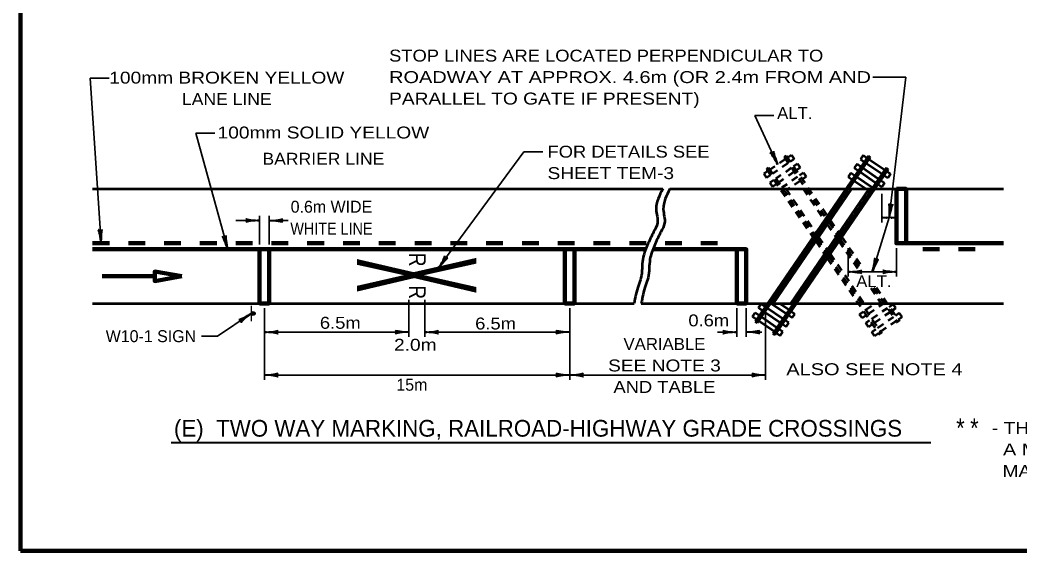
# Model space of a CAD drawing. Extents: x -90 to 765, y -1136 to -592.
# Drawn here: x -32.9 to 218.6, y -1124.2 to -990.6 of the extents above; entities that cross this region are included whole.
import ezdxf
from ezdxf.enums import TextEntityAlignment as Align

# ---------------------------------------------------------------- set-up
doc = ezdxf.new("R2010")
doc.units = 0
doc.header["$LTSCALE"] = 1.2
doc.linetypes.add('SHORT_DASHED', pattern=[2.7, 1.5, -1.2])
doc.layers.add('1', color=7, linetype='Continuous', lineweight=90)
doc.layers.add('4', color=7, linetype='Continuous', lineweight=25)

msp = doc.modelspace()

# ---------------------------------------------------------------- hatches: boundary and pattern name
at = {"layer": '4'}
msp.add_hatch(color=256, dxfattribs=at).paths.add_polyline_path([(25.74, -1064.932, 1), (25.74, -1063.948, 1)])

# ---------------------------------------------------------------- linework, layer by layer
at = {"layer": '1', "lineweight": 35}
for p, q in [((-15.299, -1005.233), (-10.499, -1005.233)), ((-12.544, -1046.773), (-15.299, -1005.233)), ((181.609, -1004.973), (189.928, -1004.973)), ((157.663, -1026.973), (151.918, -1014.613)), ((151.918, -1014.613), (156.718, -1014.613)), ((19.318, -1048.273), (11.319, -1019.091)), ((11.319, -1019.091), (16.119, -1019.091)), ((72.303, -1053.024), (93.792, -1023.775)), ((93.792, -1023.775), (98.592, -1023.775)), ((183.879, -1034.323), (183.879, -1041.523)), ((21.356, -1041.073), (27.356, -1041.073)), ((27.356, -1047.073), (27.356, -1039.873)), ((29.756, -1047.073), (29.756, -1039.873)), ((29.756, -1041.073), (34.556, -1041.073)), ((183.879, -1040.323), (187.556, -1040.323)), ((175.42, -1047.973), (175.42, -1055.173)), ((187.556, -1047.973), (187.556, -1055.173)), ((175.42, -1053.973), (187.556, -1053.973)), ((64.916, -1061.023), (64.916, -1070.323)), ((68.881, -1061.023), (68.881, -1070.323)), ((28.556, -1063.123), (28.556, -1081.123)), ((105.356, -1063.123), (105.356, -1081.123)), ((147.356, -1063.123), (147.356, -1070.323)), ((149.756, -1063.123), (149.756, -1070.323)), ((154.611, -1063.123), (154.611, -1081.123)), ((64.916, -1069.123), (28.556, -1069.123)), ((68.881, -1069.123), (105.356, -1069.123)), ((142.556, -1069.123), (147.356, -1069.123)), ((149.756, -1069.123), (153.711, -1069.123)), ((28.556, -1079.923), (105.356, -1079.923)), ((105.356, -1079.923), (154.611, -1079.923))]:
    msp.add_line(p, q, dxfattribs=at)
at = {"layer": '1', "lineweight": 53}
for p, q in [((180.475, -1024.784), (151.985, -1066.463)), ((180.97, -1025.123), (152.48, -1066.802)), ((179.145, -1024.602), (178.468, -1025.593)), ((178.468, -1025.593), (179.459, -1026.27)), ((179.145, -1024.602), (180.136, -1025.28)), ((180.475, -1024.784), (180.97, -1025.123)), ((180.632, -1025.618), (184.594, -1028.327)), ((184.933, -1027.832), (156.443, -1069.51)), ((185.428, -1028.17), (156.938, -1069.849)), ((177.622, -1026.831), (176.944, -1027.822)), ((176.944, -1027.822), (177.935, -1028.5)), ((177.622, -1026.831), (178.613, -1027.509)), ((179.108, -1027.847), (183.07, -1030.556)), ((179.954, -1026.609), (183.917, -1029.318)), ((184.933, -1027.832), (185.428, -1028.17)), ((185.09, -1028.666), (186.08, -1029.343)), ((176.098, -1029.06), (175.42, -1030.051)), ((175.42, -1030.051), (176.412, -1030.729)), ((176.098, -1029.06), (177.089, -1029.738)), ((176.907, -1031.067), (179.915, -1033.123)), ((177.584, -1030.077), (181.547, -1032.785)), ((178.43, -1028.838), (182.393, -1031.547)), ((183.566, -1030.895), (184.556, -1031.572)), ((184.412, -1029.657), (185.403, -1030.334)), ((186.08, -1029.343), (185.403, -1030.334)), ((-14.644, -1033.123), (128.756, -1033.123)), ((176.228, -1033.123), (156.541, -1061.923)), ((180.589, -1033.123), (160.902, -1061.923)), ((182.888, -1031.886), (183.879, -1032.563)), ((184.556, -1031.572), (183.879, -1032.563)), ((29.756, -1061.923), (104.156, -1061.923)), ((123.356, -1061.923), (214.442, -1061.923)), ((152.857, -1063.061), (153.534, -1062.07)), ((153.847, -1063.738), (152.857, -1063.061)), ((154.525, -1062.747), (153.534, -1062.07)), ((158.982, -1065.795), (155.02, -1063.086)), ((159.829, -1064.557), (155.977, -1061.923)), ((160.506, -1063.566), (158.104, -1061.923)), ((161.993, -1064.582), (161.001, -1063.905)), ((151.333, -1065.29), (152.01, -1064.299)), ((152.323, -1065.967), (151.333, -1065.29)), ((151.985, -1066.463), (152.48, -1066.802)), ((153.001, -1064.976), (152.01, -1064.299)), ((156.781, -1069.015), (152.819, -1066.306)), ((157.459, -1068.024), (153.496, -1065.315)), ((158.305, -1066.786), (154.343, -1064.077)), ((160.469, -1066.811), (159.478, -1066.134)), ((161.315, -1065.573), (160.324, -1064.895)), ((161.315, -1065.573), (161.993, -1064.582)), ((158.945, -1069.04), (157.954, -1068.363)), ((158.267, -1070.031), (158.945, -1069.04)), ((159.791, -1067.802), (158.8, -1067.124)), ((159.791, -1067.802), (160.469, -1066.811)), ((156.443, -1069.51), (156.938, -1069.849)), ((158.267, -1070.031), (157.277, -1069.353))]:
    msp.add_line(p, q, dxfattribs=at)
at = {"layer": '1', "linetype": 'SHORT_DASHED', "lineweight": 53}
for p, q in [((159.644, -1025.618), (155.682, -1028.327)), ((159.801, -1024.784), (159.306, -1025.123)), ((159.306, -1025.123), (169.775, -1040.438)), ((159.801, -1024.784), (170.138, -1039.906)), ((161.13, -1024.602), (160.14, -1025.28)), ((161.808, -1025.593), (160.817, -1026.27)), ((161.13, -1024.602), (161.808, -1025.593)), ((155.186, -1028.666), (154.196, -1029.343)), ((155.343, -1027.832), (154.847, -1028.17)), ((154.847, -1028.17), (166.504, -1045.223)), ((155.343, -1027.832), (166.867, -1044.691)), ((160.322, -1026.609), (156.359, -1029.318)), ((161.168, -1027.847), (157.206, -1030.556)), ((162.654, -1026.831), (161.663, -1027.509)), ((163.332, -1027.822), (162.341, -1028.5)), ((162.654, -1026.831), (163.332, -1027.822)), ((154.196, -1029.343), (154.873, -1030.334)), ((155.864, -1029.657), (154.873, -1030.334)), ((156.71, -1030.895), (155.72, -1031.572)), ((161.845, -1028.838), (157.883, -1031.547)), ((162.692, -1030.077), (158.729, -1032.785)), ((163.369, -1031.067), (160.361, -1033.123)), ((164.178, -1029.06), (163.187, -1029.738)), ((164.855, -1030.051), (163.864, -1030.729)), ((164.178, -1029.06), (164.855, -1030.051)), ((155.72, -1031.572), (156.397, -1032.563)), ((157.387, -1031.886), (156.397, -1032.563)), ((159.687, -1033.123), (167.231, -1044.159)), ((164.048, -1033.123), (169.411, -1040.97)), ((170.865, -1040.97), (173.045, -1044.159)), ((170.138, -1042.033), (172.318, -1045.222)), ((170.501, -1041.501), (172.682, -1044.691)), ((167.231, -1046.286), (169.411, -1049.475)), ((167.594, -1045.754), (169.775, -1048.944)), ((167.958, -1045.222), (170.138, -1048.412)), ((173.045, -1046.286), (178.002, -1053.537)), ((173.408, -1045.754), (178.632, -1053.396)), ((173.772, -1045.223), (179.165, -1053.112)), ((170.138, -1050.539), (183.338, -1069.849)), ((170.501, -1050.007), (183.833, -1069.51)), ((170.865, -1049.475), (179.374, -1061.923)), ((181.11, -1058.084), (183.734, -1061.923)), ((181.779, -1058), (187.796, -1066.802)), ((182.462, -1057.936), (188.291, -1066.463)), ((178.283, -1064.582), (179.274, -1063.905)), ((179.77, -1063.566), (182.172, -1061.923)), ((180.447, -1064.557), (184.299, -1061.923)), ((181.293, -1065.795), (185.256, -1063.086)), ((185.751, -1062.747), (186.742, -1062.07)), ((186.429, -1063.738), (187.419, -1063.061)), ((187.419, -1063.061), (186.742, -1062.07)), ((178.961, -1065.573), (178.283, -1064.582)), ((178.961, -1065.573), (179.952, -1064.895)), ((179.807, -1066.811), (180.798, -1066.134)), ((181.971, -1066.786), (185.933, -1064.077)), ((182.817, -1068.024), (186.78, -1065.315)), ((183.494, -1069.015), (187.457, -1066.306)), ((187.275, -1064.976), (188.266, -1064.299)), ((187.952, -1065.967), (188.943, -1065.29)), ((188.943, -1065.29), (188.266, -1064.299)), ((180.484, -1067.802), (179.807, -1066.811)), ((180.484, -1067.802), (181.475, -1067.124)), ((181.331, -1069.04), (182.322, -1068.363)), ((182.008, -1070.031), (181.331, -1069.04)), ((182.008, -1070.031), (182.999, -1069.353))]:
    msp.add_line(p, q, dxfattribs=at)
at = {"layer": '1'}
for p, q in [((-14.644, -1046.773), (-10.444, -1046.773)), ((-5.644, -1046.773), (-1.444, -1046.773)), ((3.356, -1046.773), (7.556, -1046.773)), ((12.356, -1046.773), (16.556, -1046.773)), ((21.356, -1046.773), (25.556, -1046.773)), ((30.356, -1046.773), (34.556, -1046.773)), ((39.356, -1046.773), (43.556, -1046.773)), ((48.356, -1046.773), (52.556, -1046.773)), ((57.356, -1046.773), (61.556, -1046.773)), ((66.356, -1046.773), (70.556, -1046.773)), ((75.356, -1046.773), (79.556, -1046.773)), ((84.356, -1046.773), (88.556, -1046.773)), ((93.356, -1046.773), (97.556, -1046.773)), ((102.356, -1046.773), (106.556, -1046.773)), ((106.556, -1048.273), (124.481, -1048.273)), ((111.356, -1046.773), (115.556, -1046.773)), ((120.356, -1046.773), (124.556, -1046.773)), ((126.281, -1048.273), (149.756, -1048.273)), ((129.356, -1046.773), (133.556, -1046.773)), ((138.356, -1046.773), (142.556, -1046.773)), ((187.556, -1046.773), (214.442, -1046.773)), ((194.156, -1048.273), (198.356, -1048.273)), ((203.156, -1048.273), (207.356, -1048.273)), ((0.956, -1055.098), (-12.244, -1055.098))]:
    msp.add_line(p, q, dxfattribs=at)
at = {"layer": '1', "lineweight": 40}
msp.add_line((5.065, -1096.892), (196.182, -1096.892), dxfattribs=at)
at = {"layer": '1', "lineweight": 158}
msp.add_line((758.78, -1124.188), (-32.82, -1124.188), dxfattribs=at)
msp.add_lwpolyline([(758.78, -598.088), (-32.92, -598.188), (-32.82, -1124.188)], dxfattribs=at)
at = {"layer": '1', "lineweight": 35}
for points in [[(181.488, -1053.973), (185.717, -1040.323), (189.928, -1004.973)], [(12.74, -1070.151), (16.798, -1070.151), (25.26, -1064.44)]]:
    msp.add_lwpolyline(points, dxfattribs=at)
at = {"layer": '1', "lineweight": 53}
for points in [[(130.556, -1033.123), (187.556, -1033.123), (214.442, -1033.123)], [(-14.644, -1061.923), (27.356, -1061.923), (29.756, -1061.923)], [(104.156, -1061.923), (106.556, -1061.923), (121.556, -1061.923)]]:
    msp.add_lwpolyline(points, dxfattribs=at)
at = {"layer": '1'}
for points in [[(187.556, -1033.123), (187.556, -1046.773), (189.956, -1046.773), (189.956, -1033.123)], [(27.356, -1061.923), (29.756, -1061.923), (29.756, -1048.273), (27.356, -1048.273)], [(104.156, -1048.273), (104.156, -1061.923), (106.556, -1061.923), (106.556, -1048.273)], [(147.356, -1061.923), (149.756, -1061.923), (149.756, -1048.273), (147.356, -1048.273)], [(7.761, -1055.098), (0.956, -1056.298), (0.956, -1053.898)]]:
    msp.add_lwpolyline(points, close=True, dxfattribs=at)
msp.add_lwpolyline([(-14.644, -1048.273), (29.756, -1048.273), (106.556, -1048.273)], dxfattribs=at)
at = {"layer": '1', "lineweight": 40}
for centre, major_axis, ratio, start_param, end_param in [((157.327, -1025.646), (0.697, -2), 0.07063, 3.1407148, 5.41811), ((156.81, -1025.925), (1.073, -1.864), 0.122415, 0.8963533, 3.1415927), ((185.543, -1038.984), (-0.067, -2.15), 0.122415, 0.8963533, 3.1415927), ((185.543, -1038.984), (-0.067, -2.15), 0.122415, 0.8963533, 3.1415927), ((186.128, -1039.018), (-0.459, -2.068), 0.07063, 3.1407148, 5.41811), ((186.128, -1039.018), (-0.459, -2.068), 0.07063, 3.1407148, 5.41811), ((26.046, -1041.405), (2.143, 0.187), 0.122415, 0.8963533, 3.1415927), ((26.046, -1041.405), (2.143, 0.187), 0.122415, 0.8963533, 3.1415927), ((26.046, -1041.405), (2.143, 0.187), 0.122415, 0.8963533, 3.1415927), ((26.011, -1040.819), (2.108, -0.211), 0.07063, 3.1407148, 5.41811), ((26.011, -1040.819), (2.108, -0.211), 0.07063, 3.1407148, 5.41811), ((26.011, -1040.819), (2.108, -0.211), 0.07063, 3.1407148, 5.41811), ((31.1, -1041.327), (-2.108, 0.211), 0.07063, 3.1407148, 5.41811), ((31.065, -1040.742), (-2.143, -0.187), 0.122415, 0.8963533, 3.1415927), ((184.39, -1040.199), (-0.83, -0.073), 0.122415, 0.8963533, 3.1415927), ((184.404, -1040.426), (-0.817, 0.082), 0.07063, 3.1407148, 5.41811), ((187.044, -1040.199), (0.83, -0.073), 0.122415, 3.1415927, 5.386832), ((187.031, -1040.426), (0.817, 0.082), 0.07063, 0.8650754, 3.1424706), ((-12.962, -1045.489), (0.329, -2.126), 0.122415, 0.8963533, 3.1415927), ((-12.38, -1045.415), (-0.071, -2.117), 0.07063, 3.1407148, 5.41811), ((18.652, -1047.098), (0.747, -2.017), 0.122415, 0.8963533, 3.1415927), ((19.208, -1046.91), (0.354, -2.088), 0.07063, 3.1407148, 5.41811), ((72.811, -1051.772), (-1.118, -1.838), 0.122415, 0.8963533, 3.1415927), ((73.304, -1052.091), (-1.418, -1.574), 0.07063, 3.1407148, 5.41811), ((181.559, -1052.624), (-0.455, -2.102), 0.122415, 0.8963533, 3.1415927), ((182.129, -1052.764), (-0.825, -1.951), 0.07063, 3.1407148, 5.41811), ((176.73, -1053.642), (-2.143, -0.187), 0.122415, 0.8963533, 3.1415927), ((186.211, -1053.719), (2.108, -0.211), 0.07063, 3.1407148, 5.41811), ((176.765, -1054.227), (-2.108, 0.211), 0.07063, 3.1407148, 5.41811), ((186.246, -1054.305), (2.143, 0.187), 0.122415, 0.8963533, 3.1415927), ((24.004, -1064.982), (1.865, 1.004), 0.07063, 3.1407148, 5.41811), ((24.361, -1065.447), (1.671, 1.354), 0.122415, 0.8963533, 3.1415927), ((29.865, -1068.792), (-2.143, -0.187), 0.122415, 0.8963533, 3.1415927), ((29.865, -1068.792), (-2.143, -0.187), 0.122415, 0.8963533, 3.1415927), ((63.571, -1068.869), (2.108, -0.211), 0.07063, 3.1407148, 5.41811), ((63.571, -1068.869), (2.108, -0.211), 0.07063, 3.1407148, 5.41811), ((70.191, -1068.792), (-2.143, -0.187), 0.122415, 0.8963533, 3.1415927), ((70.191, -1068.792), (-2.143, -0.187), 0.122415, 0.8963533, 3.1415927), ((104.011, -1068.869), (2.108, -0.211), 0.07063, 3.1407148, 5.41811), ((146.046, -1068.792), (2.143, -0.187), 0.122415, 3.1415927, 5.386832), ((146.046, -1068.792), (2.143, -0.187), 0.122415, 3.1415927, 5.386832), ((146.046, -1068.792), (2.143, -0.187), 0.122415, 3.1415927, 5.386832), ((151.1, -1068.869), (-2.108, -0.211), 0.07063, 0.8650754, 3.1424706), ((29.9, -1069.377), (-2.108, 0.211), 0.07063, 3.1407148, 5.41811), ((29.9, -1069.377), (-2.108, 0.211), 0.07063, 3.1407148, 5.41811), ((63.606, -1069.455), (2.143, 0.187), 0.122415, 0.8963533, 3.1415927), ((63.606, -1069.455), (2.143, 0.187), 0.122415, 0.8963533, 3.1415927), ((70.226, -1069.377), (-2.108, 0.211), 0.07063, 3.1407148, 5.41811), ((70.226, -1069.377), (-2.108, 0.211), 0.07063, 3.1407148, 5.41811), ((104.046, -1069.455), (2.143, 0.187), 0.122415, 0.8963533, 3.1415927), ((146.011, -1069.377), (2.108, 0.211), 0.07063, 0.8650754, 3.1424706), ((146.011, -1069.377), (2.108, 0.211), 0.07063, 0.8650754, 3.1424706), ((146.011, -1069.377), (2.108, 0.211), 0.07063, 0.8650754, 3.1424706), ((151.065, -1069.455), (-2.143, 0.187), 0.122415, 3.1415927, 5.386832), ((29.9, -1080.177), (-2.108, 0.211), 0.07063, 3.1407148, 5.41811), ((29.865, -1079.592), (-2.143, -0.187), 0.122415, 0.8963533, 3.1415927), ((104.046, -1080.255), (2.143, 0.187), 0.122415, 0.8963533, 3.1415927), ((104.011, -1079.669), (2.108, -0.211), 0.07063, 3.1407148, 5.41811), ((106.7, -1080.177), (-2.108, 0.211), 0.07063, 3.1407148, 5.41811), ((106.7, -1080.177), (-2.108, 0.211), 0.07063, 3.1407148, 5.41811), ((106.665, -1079.592), (-2.143, -0.187), 0.122415, 0.8963533, 3.1415927), ((106.665, -1079.592), (-2.143, -0.187), 0.122415, 0.8963533, 3.1415927), ((153.301, -1080.255), (2.143, 0.187), 0.122415, 0.8963533, 3.1415927), ((153.266, -1079.669), (2.108, -0.211), 0.07063, 3.1407148, 5.41811)]:
    msp.add_ellipse(centre, major_axis=major_axis, ratio=ratio, start_param=start_param, end_param=end_param, dxfattribs=at)
at = {"layer": '1', "lineweight": 53}
for points in [[(128.756, -1033.123), (127.097, -1038.225), (127.416, -1041.736), (126.459, -1043.971), (124.863, -1047.322), (123.747, -1050.834), (123.268, -1055.462), (122.63, -1057.377), (121.556, -1061.923)], [(130.556, -1033.123), (128.897, -1038.225), (129.216, -1041.736), (128.259, -1043.971), (126.663, -1047.322), (125.547, -1050.834), (125.068, -1055.462), (124.43, -1057.377), (123.356, -1061.923)]]:
    msp.add_spline(points, degree=3, dxfattribs=at)
at = {"layer": '4'}
msp.add_line((25.26, -1062.52), (25.26, -1066.36), dxfattribs=at)
msp.add_circle((25.74, -1064.44), 0.492, dxfattribs=at)

# ---------------------------------------------------------------- texts
at = {"layer": '1'}
for s, width, p in [('STOP LINES ARE LOCATED PERPENDICULAR TO', 1.15, (59.925, -1001.082)), ('ROADWAY AT APPROX. 4.6m (OR 2.4m FROM AND', 1.25, (59.925, -1006.482)), ('PARALLEL TO GATE IF PRESENT)', 1.2, (59.925, -1011.882)), ('FOR DETAILS SEE', 1.15, (99.771, -1025.237)), ('SHEET TEM-3', 1.2, (99.771, -1030.637)), ('- THIS DISTANCE MAY BE REDUCED TO A MINIMUM OF 15m DEPENDING UPON LOCAL CONDITIONS.', 1.2, (211.554, -1094.758)), ('  A MINIMUM OF 30m IS GENERALLY NECESSARY FOR THE EFFECTIVE DISPLAY OF PAVEMENT', 1.25, (211.554, -1100.158)), ('  MARKINGS. IF THE 30m MINIMUM CANNOT BE OBTAINED, MARKINGS MAY BE OMITTED.', 1.2, (211.554, -1105.558))]:
    msp.add_text(s, height=3, dxfattribs=dict(at, width=width)).set_placement(p)
for s, height, width, p in [('100mm BROKEN YELLOW', 3, 1.2, (19.105, -1006.618)), ('LANE LINE', 3, 1.1, (19.105, -1012.018)), ('ALT.', 3, 1.05, (161.979, -1015.529)), ('100mm SOLID YELLOW', 3, 1.2, (43.4, -1020.426)), ('BARRIER LINE', 3, 1.1, (43.4, -1027.026)), ('WHITE LINE', 3, 0.9, (45.421, -1044.589)), ('ALT.', 3, 1.05, (181.869, -1057.822)), ('6.5m', 3, 1.15, (47.64, -1068.292)), ('6.5m', 3, 1.15, (86.702, -1068.469)), ('0.6m', 3, 1.15, (140.337, -1067.68)), ('2.0m', 3, 1.2, (66.515, -1073.815)), ('VARIABLE', 3, 1.05, (129.183, -1073.622)), ('SEE NOTE 3', 3, 1.2, (129.183, -1079.022)), ('ALSO SEE NOTE 4', 3, 1.25, (182.004, -1079.964)), ('AND TABLE', 3, 1.15, (129.183, -1084.422)), ('*', 4.8, 0.85, (203.633, -1095.644)), ('*', 4.8, 0.85, (207.145, -1095.644))]:
    msp.add_text(s, height=height, dxfattribs=dict(at, width=width)).set_placement(p, align=Align.CENTER)
for s, p in [('0.6m WIDE', (45.421, -1039.089)), ('W10-1 SIGN', (0.014, -1071.651)), ('15m', (65.652, -1083.864))]:
    msp.add_text(s, height=3, dxfattribs=at).set_placement(p, align=Align.CENTER)
at = {"layer": '1', "width": 0.35}
msp.add_text('X', height=30, rotation=90, dxfattribs=at).set_placement((81.829, -1059.535))
at = {"layer": '1', "width": 0.85}
for p in [(64.953, -1050.911), (64.92, -1059.1)]:
    msp.add_text('R', height=4.2, rotation=270, dxfattribs=at).set_placement(p, align=Align.CENTER)
at = {"layer": '1'}
msp.add_text('(E)  TWO WAY MARKING, RAILROAD-HIGHWAY GRADE CROSSINGS', height=4.2, dxfattribs=at).set_placement((5.801, -1095.421))

doc.saveas('drawing.dxf')
